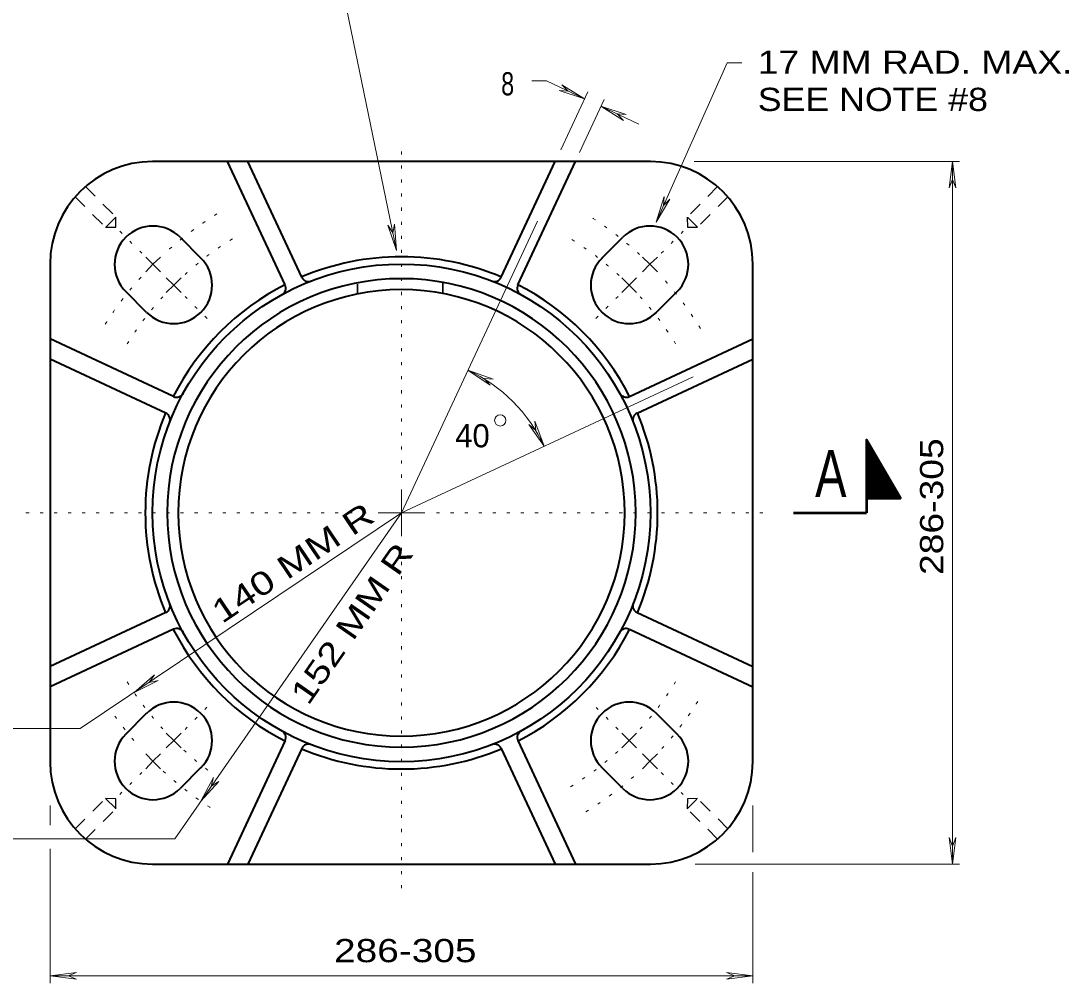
# Model space of a CAD drawing. Extents: x 312583 to 312854, y 144419 to 144597.
# Drawn here: x 312679.84 to 312714.15, y 144498.77 to 144530.27 of the extents above; entities that cross this region are included whole.
import ezdxf
from ezdxf.enums import TextEntityAlignment as Align

# ---------------------------------------------------------------- set-up
doc = ezdxf.new("R2010")
doc.units = 0
doc.header["$LTSCALE"] = 0.3
doc.linetypes.add('DOTTED', pattern=[1.5, 0.3, -1.2])
doc.linetypes.add('SHORT_DASHED', pattern=[2.7, 1.5, -1.2])
doc.layers.add('1', color=7, linetype='Continuous', lineweight=35)
doc.layers.add('2', color=7, linetype='Continuous', lineweight=13)

msp = doc.modelspace()

# ---------------------------------------------------------------- linework, layer by layer
at = {"layer": '1', "lineweight": 40}
for p, q in [((312692.2955, 144525.6633), (312684.1535, 144525.6633)), ((312688.4851, 144521.623), (312686.5991, 144525.6633)), ((312689.0295, 144521.876), (312687.2661, 144525.6633)), ((312700.4451, 144525.6633), (312692.2955, 144525.6633)), ((312695.5615, 144521.876), (312697.3248, 144525.6633)), ((312696.1058, 144521.623), (312697.9918, 144525.6633)), ((312685.0505, 144523.187), (312685.7328, 144522.5046)), ((312698.8581, 144522.5046), (312699.5405, 144523.187)), ((312680.7955, 144522.3053), (312680.7955, 144514.1633)), ((312703.7955, 144514.1633), (312703.7955, 144522.3053)), ((312683.9541, 144520.726), (312683.2718, 144521.4083)), ((312701.3191, 144521.4083), (312700.6368, 144520.726)), ((312684.8358, 144517.9736), (312680.7955, 144519.8596)), ((312699.7551, 144517.9736), (312703.7955, 144519.8596)), ((312684.5828, 144517.4293), (312680.7955, 144519.1926)), ((312700.0081, 144517.4293), (312703.7955, 144519.1926)), ((312680.7955, 144514.1633), (312680.7955, 144506.0136)), ((312703.7955, 144506.0136), (312703.7955, 144514.1633)), ((312684.5828, 144510.8973), (312680.7955, 144509.134)), ((312700.0081, 144510.8973), (312703.7955, 144509.134)), ((312684.8358, 144510.353), (312680.7955, 144508.467)), ((312699.7551, 144510.353), (312703.7955, 144508.467)), ((312683.2718, 144506.9183), (312683.9541, 144507.6006)), ((312700.6368, 144507.6006), (312701.3191, 144506.9183)), ((312688.4851, 144506.7036), (312686.5991, 144502.6633)), ((312689.0295, 144506.4506), (312687.2661, 144502.6633)), ((312695.5615, 144506.4506), (312697.3248, 144502.6633)), ((312696.1058, 144506.7036), (312697.9918, 144502.6633)), ((312685.7328, 144505.822), (312685.0505, 144505.1396)), ((312699.5405, 144505.1396), (312698.8581, 144505.822)), ((312684.1535, 144502.6633), (312692.2955, 144502.6633)), ((312692.2955, 144502.6633), (312700.4451, 144502.6633))]:
    msp.add_line(p, q, dxfattribs=at)
at = {"layer": '1', "linetype": 'SHORT_DASHED', "lineweight": 25}
for p, q in [((312681.9531, 144524.843), (312682.9498, 144523.8463)), ((312702.6378, 144524.843), (312701.6488, 144523.8463)), ((312681.6158, 144524.5056), (312682.6125, 144523.509)), ((312702.9751, 144524.5056), (312701.9861, 144523.509)), ((312681.6158, 144503.821), (312682.6125, 144504.81)), ((312702.9751, 144503.821), (312701.9861, 144504.81)), ((312681.9531, 144503.4836), (312682.9498, 144504.4726)), ((312702.6378, 144503.4836), (312701.6488, 144504.4726))]:
    msp.add_line(p, q, dxfattribs=at)
for points in [[(312682.9498, 144523.8463), (312682.6125, 144523.509), (312682.9421, 144523.5166)], [(312701.9861, 144523.509), (312701.6488, 144523.8463), (312701.6565, 144523.5166)], [(312682.6125, 144504.81), (312682.9498, 144504.4726), (312682.9421, 144504.8023)], [(312701.6488, 144504.4726), (312701.9861, 144504.81), (312701.6565, 144504.8023)]]:
    msp.add_lwpolyline(points, close=True, dxfattribs=at)
at = {"layer": '1', "lineweight": 40}
for centre, radius, start, end in [((312684.1496, 144522.3072), 3.3542, 90, 180), ((312700.4413, 144522.3072), 3.3542, 0, 90), ((312684.163, 144522.2938), 1.2578, 45, 225), ((312700.4279, 144522.2938), 1.2578, 315, 135), ((312684.8416, 144521.6153), 1.2578, 225, 45), ((312692.2955, 144514.1614), 8.3854, 90, 112.94673), ((312692.2879, 144514.1611), 8.3854, 67, 89.94673), ((312699.7494, 144521.6153), 1.2578, 135, 315), ((312689.2485, 144521.9736), 0.2396, 205.00333, 291.30722), ((312695.3425, 144521.9736), 0.2396, 248.69278, 334.99667), ((312692.2955, 144514.1614), 7.6667, 90, 180), ((312692.2955, 144514.1614), 8.3854, 117.05705, 152.95096), ((312688.2701, 144521.5175), 0.2396, 298.68804, 25.01264), ((312692.2955, 144514.1614), 7.6667, 0, 90), ((312696.3208, 144521.5175), 0.2396, 154.98736, 241.31196), ((312692.2955, 144514.1614), 8.3854, 27.05705, 62.95096), ((312692.2955, 144514.1614), 7.3073, 90, 180), ((312692.2955, 144514.1614), 7.3073, 0, 90), ((312684.9394, 144518.1867), 0.2396, 244.98736, 331.31196), ((312699.6515, 144518.1867), 0.2396, 208.68804, 295.01264), ((312692.2955, 144514.1614), 8.3854, 157.05327, 180), ((312684.4832, 144517.2084), 0.2396, 338.69278, 64.99667), ((312700.1077, 144517.2084), 0.2396, 115.00333, 201.30722), ((312692.2955, 144514.1614), 8.3854, 0, 22.94673), ((312692.2955, 144514.1614), 8.3854, 180, 202.94673), ((312692.2955, 144514.1614), 7.6667, 180, 270), ((312692.2955, 144514.1614), 7.3073, 180, 270), ((312692.2955, 144514.1614), 7.6667, 270, 0), ((312692.2955, 144514.1614), 7.3073, 270, 0), ((312692.2955, 144514.1614), 8.3854, 337.05327, 0), ((312684.4832, 144511.1144), 0.2396, 295.00333, 21.30722), ((312700.1077, 144511.1144), 0.2396, 158.69278, 244.99667), ((312692.2955, 144514.1614), 8.3854, 207.05705, 242.95096), ((312684.9394, 144510.136), 0.2396, 28.68804, 115.01264), ((312692.2955, 144514.1614), 8.3854, 297.05705, 332.95096), ((312699.6515, 144510.136), 0.2396, 64.98736, 151.31196), ((312684.8416, 144506.7075), 1.2578, 315, 135), ((312699.7494, 144506.7075), 1.2578, 45, 225), ((312684.163, 144506.029), 1.2578, 135, 315), ((312688.2701, 144506.8053), 0.2396, 334.98736, 61.31196), ((312696.3208, 144506.8053), 0.2396, 118.68804, 205.01264), ((312700.4279, 144506.029), 1.2578, 225, 45), ((312692.2955, 144514.1614), 8.3854, 247.05327, 270), ((312689.2485, 144506.3491), 0.2396, 68.69278, 154.99667), ((312692.2955, 144514.1614), 8.3854, 270, 292.94673), ((312695.3425, 144506.3491), 0.2396, 25.00333, 111.30722), ((312684.1496, 144506.0156), 3.3542, 180, 270), ((312700.4413, 144506.0156), 3.3542, 270, 0)]:
    msp.add_arc(centre, radius, start, end, dxfattribs=at)
at = {"layer": '1', "linetype": 'DOTTED', "lineweight": 13}
for radius, start, end in [(11.5, 121.67302, 132.67646), (11.5, 47.32354, 58.32698), (10.5417, 121.67021, 132.50277), (10.5417, 47.49723, 58.32979), (11.5, 137.83702, 148.35019), (11.5, 31.64981, 42.16298), (10.5417, 137.83921, 148.35431), (10.5417, 31.64569, 42.16079), (10.5417, 211.64569, 222.16079), (10.5417, 317.83921, 328.35431), (11.5, 317.83702, 328.35019), (11.5, 215.3347, 222.16255), (10.5417, 227.49787, 233.37708), (10.5417, 301.67021, 312.50277), (11.5, 227.32354, 238.32698), (11.5, 301.67302, 312.67646)]:
    msp.add_arc((312692.2955, 144514.1614), radius, start, end, dxfattribs=at)
at = {"layer": '2'}
for p, q in [((312697.0411, 144528.3006), (312696.5581, 144528.3006)), ((312698.2831, 144527.718), (312697.0411, 144528.3006)), ((312697.5471, 144528.178), (312697.7541, 144527.9633)), ((312698.2831, 144527.718), (312697.5471, 144528.178)), ((312697.4551, 144527.9863), (312697.7541, 144527.9633)), ((312698.2831, 144527.718), (312697.4551, 144527.9863)), ((312697.5088, 144526.0466), (312698.3905, 144527.948)), ((312698.1221, 144525.9546), (312698.9348, 144527.695)), ((312698.8198, 144527.4726), (312700.0695, 144526.89)), ((312698.8198, 144527.4726), (312699.6478, 144527.2043)), ((312698.8198, 144527.4726), (312699.5635, 144527.005)), ((312699.6478, 144527.2043), (312699.3565, 144527.2196)), ((312699.5635, 144527.005), (312699.3565, 144527.2196)), ((312701.8788, 144525.6633), (312710.5651, 144525.6633)), ((312710.3275, 144525.6633), (312710.2201, 144524.797)), ((312710.3275, 144525.6633), (312710.4348, 144524.797)), ((312710.2201, 144524.797), (312710.3275, 144525.073)), ((312710.4348, 144524.797), (312710.3275, 144525.073)), ((312700.6368, 144523.6776), (312700.8898, 144524.5133)), ((312700.6368, 144523.6776), (312701.0815, 144524.429)), ((312700.8898, 144524.5133), (312700.8745, 144524.222)), ((312701.0815, 144524.429), (312700.8745, 144524.222)), ((312692.0655, 144523.6163), (312692.0118, 144523.325)), ((312692.1345, 144522.75), (312692.0655, 144523.6163)), ((312692.2955, 144514.1633), (312696.7498, 144523.716)), ((312691.8508, 144523.578), (312692.0118, 144523.325)), ((312692.1345, 144522.75), (312691.8508, 144523.578)), ((312684.1611, 144522.2976), (312683.9235, 144522.5353)), ((312684.1611, 144522.2976), (312683.9235, 144522.0523)), ((312684.1611, 144522.2976), (312684.4065, 144522.5353)), ((312684.1611, 144522.2976), (312684.4065, 144522.0523)), ((312700.4298, 144522.2976), (312700.1845, 144522.5353)), ((312700.4298, 144522.2976), (312700.1845, 144522.0523)), ((312700.4298, 144522.2976), (312700.6751, 144522.5353)), ((312700.4298, 144522.2976), (312700.6751, 144522.0523)), ((312684.8435, 144521.6153), (312684.5981, 144521.8606)), ((312684.8435, 144521.6153), (312684.5981, 144521.37)), ((312684.8435, 144521.6153), (312685.0888, 144521.8606)), ((312684.8435, 144521.6153), (312685.0888, 144521.37)), ((312699.7475, 144521.6153), (312699.5098, 144521.8606)), ((312699.7475, 144521.6153), (312699.5098, 144521.37)), ((312699.7475, 144521.6153), (312699.9928, 144521.8606)), ((312699.7475, 144521.6153), (312699.9928, 144521.37)), ((312694.4728, 144518.8323), (312695.2011, 144518.3416)), ((312694.4728, 144518.8323), (312695.2931, 144518.5333)), ((312692.2955, 144514.1633), (312701.8481, 144518.6176)), ((312695.2011, 144518.3416), (312695.0018, 144518.564)), ((312695.2931, 144518.5333), (312695.0018, 144518.564)), ((312696.6578, 144517.161), (312696.6885, 144516.862)), ((312696.9645, 144516.3406), (312696.6578, 144517.161)), ((312696.4661, 144517.0536), (312696.6885, 144516.862)), ((312696.9645, 144516.3406), (312696.4661, 144517.0536)), ((312692.2955, 144514.1633), (312692.2955, 144514.93)), ((312692.2955, 144514.1633), (312692.2955, 144514.93)), ((312692.2955, 144514.1633), (312681.7845, 144507.1023)), ((312692.2955, 144514.1633), (312684.8741, 144503.4913)), ((312692.2955, 144514.1633), (312691.5288, 144514.1633)), ((312692.2955, 144514.1633), (312693.0621, 144514.1633)), ((312692.2955, 144514.1633), (312692.2955, 144513.3966)), ((312683.5478, 144508.283), (312684.2071, 144508.858)), ((312684.2071, 144508.858), (312684.0385, 144508.6126)), ((312683.5478, 144508.283), (312684.3298, 144508.674)), ((312684.3298, 144508.674), (312684.0385, 144508.6126)), ((312681.7845, 144507.1023), (312678.6335, 144507.1023)), ((312684.8435, 144506.7113), (312684.5981, 144506.949)), ((312684.8435, 144506.7113), (312684.5981, 144506.949)), ((312684.8435, 144506.7113), (312685.0888, 144506.949)), ((312699.7475, 144506.7113), (312699.5098, 144506.949)), ((312699.7475, 144506.7113), (312699.9928, 144506.949)), ((312684.8435, 144506.7113), (312684.5981, 144506.466)), ((312684.8435, 144506.7113), (312685.0888, 144506.466)), ((312699.7475, 144506.7113), (312699.5098, 144506.466)), ((312699.7475, 144506.7113), (312699.9928, 144506.466)), ((312684.1611, 144506.029), (312683.9235, 144506.2743)), ((312684.1611, 144506.029), (312683.9235, 144506.2743)), ((312684.1611, 144506.029), (312684.4065, 144506.2743)), ((312700.4298, 144506.029), (312700.1845, 144506.2743)), ((312700.4298, 144506.029), (312700.6751, 144506.2743)), ((312684.1611, 144506.029), (312683.9235, 144505.7836)), ((312684.1611, 144506.029), (312684.4065, 144505.7836)), ((312700.4298, 144506.029), (312700.1845, 144505.7836)), ((312700.4298, 144506.029), (312700.6751, 144505.7836)), ((312685.7328, 144504.718), (312686.1391, 144505.4923)), ((312686.1391, 144505.4923), (312686.0701, 144505.2086)), ((312685.7328, 144504.718), (312686.3155, 144505.3696)), ((312686.3155, 144505.3696), (312686.0701, 144505.2086)), ((312680.7955, 144504.58), (312680.7955, 144503.936)), ((312703.7955, 144504.58), (312703.7955, 144503.0543)), ((312684.8741, 144503.4913), (312678.6335, 144503.4913)), ((312710.2201, 144503.5296), (312710.3275, 144503.2536)), ((312710.3275, 144502.6633), (312710.2201, 144503.5296)), ((312710.4348, 144503.5296), (312710.3275, 144503.2536)), ((312710.3275, 144502.6633), (312710.4348, 144503.5296)), ((312680.7955, 144503.1616), (312680.7955, 144498.7686)), ((312701.9095, 144502.6633), (312710.5651, 144502.6633)), ((312703.7955, 144502.4026), (312703.7955, 144498.7686)), ((312680.7955, 144499.0063), (312681.6618, 144499.1136)), ((312680.7955, 144499.0063), (312703.7955, 144499.0063)), ((312680.7955, 144499.0063), (312681.6618, 144498.899)), ((312681.6618, 144499.1136), (312681.3858, 144499.0063)), ((312681.6618, 144498.899), (312681.3858, 144499.0063)), ((312702.9291, 144499.1136), (312703.2051, 144499.0063)), ((312703.7955, 144499.0063), (312702.9291, 144499.1136)), ((312702.9291, 144498.899), (312703.2051, 144499.0063)), ((312703.7955, 144499.0063), (312702.9291, 144498.899))]:
    msp.add_line(p, q, dxfattribs=at)
at = {"layer": '2', "linetype": 'DOTTED'}
for p, q in [((312692.2955, 144515.3133), (312692.2955, 144526.338)), ((312683.8008, 144522.658), (312683.0265, 144523.4323)), ((312700.7978, 144522.658), (312701.5645, 144523.4323)), ((312685.2115, 144521.2473), (312686.0701, 144520.3886)), ((312699.3871, 144521.2473), (312698.5208, 144520.3886)), ((312691.1455, 144514.1633), (312679.9215, 144514.1633)), ((312693.4455, 144514.1633), (312704.4548, 144514.1633)), ((312692.2955, 144513.0133), (312692.2955, 144501.8736)), ((312685.2115, 144507.0716), (312686.0701, 144507.938)), ((312699.3871, 144507.0716), (312698.5208, 144507.938)), ((312683.8008, 144505.661), (312683.0265, 144504.8943)), ((312700.7978, 144505.661), (312701.5645, 144504.8943))]:
    msp.add_line(p, q, dxfattribs=at)
at = {"layer": '2', "lineweight": 35}
for p, q in [((312690.8541, 144521.324), (312690.8541, 144521.6536)), ((312693.6525, 144521.3623), (312693.6525, 144521.738)), ((312707.5138, 144516.54), (312707.5291, 144516.54)), ((312707.5138, 144516.5093), (312707.5368, 144516.517)), ((312707.5138, 144516.4786), (312707.5521, 144516.5016)), ((312707.5138, 144516.4556), (312707.5598, 144516.4786)), ((312707.5138, 144516.425), (312707.5751, 144516.4556)), ((312707.5138, 144516.402), (312707.5828, 144516.4403)), ((312707.5138, 144516.3713), (312707.5981, 144516.4173)), ((312707.5138, 144516.3406), (312707.6058, 144516.3943)), ((312707.5138, 144516.31), (312707.6211, 144516.379)), ((312707.5138, 144516.287), (312707.6288, 144516.356)), ((312707.5138, 144516.264), (312707.6441, 144516.333)), ((312707.5138, 144516.2333), (312707.6518, 144516.31)), ((312707.5138, 144516.2103), (312707.6671, 144516.2946)), ((312707.5138, 144516.1796), (312707.6825, 144516.2716)), ((312707.5138, 144516.149), (312707.6901, 144516.2486)), ((312707.5138, 144516.1183), (312707.7055, 144516.2333)), ((312707.5138, 144516.0953), (312707.7208, 144516.2103)), ((312707.5138, 144516.0646), (312707.7285, 144516.1873)), ((312707.5138, 144516.0416), (312707.7438, 144516.172)), ((312707.5138, 144516.011), (312707.7515, 144516.149)), ((312707.5138, 144515.9803), (312707.7668, 144516.126)), ((312707.5138, 144515.9573), (312707.7745, 144516.1106)), ((312707.5138, 144515.9266), (312707.7898, 144516.08)), ((312707.5138, 144515.9036), (312707.7975, 144516.0646)), ((312707.5138, 144515.873), (312707.8128, 144516.0416)), ((312707.5138, 144515.8423), (312707.8205, 144516.0186)), ((312707.5138, 144515.8193), (312707.8358, 144516.0033)), ((312707.5138, 144515.7886), (312707.8435, 144515.9803)), ((312707.5138, 144515.7656), (312707.8588, 144515.9573)), ((312707.5138, 144515.735), (312707.8741, 144515.942)), ((312707.5138, 144515.712), (312707.8818, 144515.919)), ((312707.5138, 144515.6813), (312707.8971, 144515.896)), ((312707.5138, 144515.6506), (312707.9125, 144515.8806)), ((312707.5138, 144515.62), (312707.9201, 144515.8576)), ((312707.5138, 144515.597), (312707.9355, 144515.8346)), ((312707.5138, 144515.574), (312707.9431, 144515.8116)), ((312707.5138, 144515.5433), (312707.9585, 144515.7963)), ((312707.5138, 144515.5126), (312707.9661, 144515.7733)), ((312707.5138, 144515.4896), (312707.9815, 144515.7503)), ((312707.5138, 144515.459), (312707.9891, 144515.735)), ((312707.5138, 144515.4283), (312708.0045, 144515.712)), ((312707.5138, 144515.4053), (312708.0121, 144515.689)), ((312707.5138, 144515.3746), (312708.0275, 144515.6736)), ((312707.5138, 144515.344), (312708.0351, 144515.6506)), ((312707.5138, 144515.321), (312708.0505, 144515.6276)), ((312707.5138, 144515.2673), (312708.0735, 144515.5816)), ((312707.5138, 144515.2366), (312708.0888, 144515.5663)), ((312707.5138, 144515.2136), (312708.0965, 144515.5433)), ((312707.5138, 144515.183), (312708.1118, 144515.5203)), ((312707.5138, 144515.1523), (312708.1195, 144515.505)), ((312707.5138, 144515.1216), (312708.1348, 144515.482)), ((312707.5138, 144515.0986), (312708.1425, 144515.459)), ((312707.5138, 144515.0756), (312708.1578, 144515.4436)), ((312707.5138, 144515.0143), (312708.1808, 144515.3976)), ((312707.5138, 144514.9913), (312708.1885, 144515.3823)), ((312707.5138, 144514.9606), (312708.2038, 144515.3593)), ((312707.5215, 144515.2903), (312708.0658, 144515.6123)), ((312707.5215, 144515.045), (312708.1655, 144515.4206)), ((312707.5138, 144514.93), (312708.2191, 144515.3363)), ((312707.5138, 144514.907), (312708.2268, 144515.3133)), ((312707.5138, 144514.8763), (312708.2421, 144515.298)), ((312707.5138, 144514.8456), (312708.2575, 144515.275)), ((312707.5138, 144514.769), (312708.2881, 144515.2136)), ((312707.5138, 144514.7383), (312708.3035, 144515.1906)), ((312707.5138, 144514.7153), (312708.3111, 144515.1753)), ((312707.5138, 144514.6846), (312708.3265, 144515.1523)), ((312707.5138, 144514.654), (312708.3341, 144515.1293)), ((312707.5215, 144514.8226), (312708.2651, 144515.252)), ((312707.5215, 144514.792), (312708.2805, 144515.2366)), ((312707.5368, 144514.6386), (312708.3495, 144515.114)), ((312707.5905, 144514.6386), (312708.3571, 144515.0833)), ((312707.6288, 144514.6386), (312708.3725, 144515.068)), ((312707.6825, 144514.6386), (312708.3801, 144515.045)), ((312707.7285, 144514.6386), (312708.3955, 144515.022)), ((312707.7745, 144514.6386), (312708.4108, 144515.0066)), ((312707.8205, 144514.6386), (312708.4185, 144514.9836)), ((312707.8741, 144514.6386), (312708.4338, 144514.9606)), ((312707.9201, 144514.6386), (312708.4491, 144514.9453)), ((312707.9661, 144514.6386), (312708.4568, 144514.9223)), ((312708.0198, 144514.6386), (312708.4721, 144514.907)), ((312708.0658, 144514.6386), (312708.4798, 144514.884)), ((312708.1118, 144514.6386), (312708.4951, 144514.861)), ((312708.1655, 144514.6386), (312708.5028, 144514.8456)), ((312708.2115, 144514.6386), (312708.5181, 144514.815)), ((312708.2575, 144514.6386), (312708.5258, 144514.7996)), ((312708.3035, 144514.6386), (312708.5411, 144514.7766)), ((312708.3571, 144514.6386), (312708.5488, 144514.7536)), ((312708.3955, 144514.6386), (312708.5641, 144514.7383)), ((312708.4491, 144514.6386), (312708.5718, 144514.7153)), ((312708.4951, 144514.6386), (312708.5871, 144514.6923)), ((312708.5488, 144514.6386), (312708.6025, 144514.677)), ((312708.5948, 144514.6386), (312708.6101, 144514.654))]:
    msp.add_line(p, q, dxfattribs=at)
at = {"layer": '2', "lineweight": 53}
for p in [(312707.5138, 144514.6386), (312705.1218, 144514.1633)]:
    msp.add_line(p, (312707.5138, 144514.1633), dxfattribs=at)
at = {"layer": '2'}
for points in [[(312680.8338, 144535.4536), (312689.5201, 144535.4536), (312692.1345, 144522.75)], [(312700.6368, 144523.6776), (312702.9521, 144528.891), (312703.4351, 144528.891)], [(312710.3275, 144502.6633), (312710.3275, 144520.9406), (312710.3275, 144525.6633)]]:
    msp.add_lwpolyline(points, dxfattribs=at)
at = {"layer": '2', "lineweight": 53}
msp.add_lwpolyline([(312707.5138, 144514.6386), (312708.6255, 144514.6386), (312707.5138, 144516.5553)], close=True, dxfattribs=at)
at = {"layer": '2', "lineweight": 40}
msp.add_circle((312692.2955, 144514.1614), 8.1458, dxfattribs=at)
at = {"layer": '2'}
msp.add_circle((312695.527, 144517.1859), 0.1833, dxfattribs=at)
msp.add_arc((312692.2955, 144514.1614), 5.1536, 25.00431, 65.00757, dxfattribs=at)

# ---------------------------------------------------------------- texts
for s, width, p in [('17 MM RAD. MAX.', 1.2, (312703.9565, 144528.5373)), ('8', 0.75, (312695.5595, 144527.8282)), ('SEE NOTE #8', 1.15, (312703.9565, 144527.3173)), ('286-305 ', 1.25, (312690.0889, 144499.451))]:
    msp.add_text(s, height=0.76, dxfattribs=dict(at, width=width)).set_placement(p)
msp.add_text('40', height=0.76, dxfattribs=at).set_placement((312694.0539, 144516.3066))
for s, rotation, width, p in [('286-305', 90, 1.2, (312710.027, 144512.1265)), ('140 MM R', 33.904, 1.3, (312686.4216, 144510.5151)), ('152 MM R', 55.183, 1.3, (312689.2432, 144507.8257))]:
    msp.add_text(s, height=0.76, rotation=rotation, dxfattribs=dict(at, width=width)).set_placement(p)
at = {"layer": '2', "width": 0.75}
msp.add_text('A', height=1.533, dxfattribs=at).set_placement((312706.3484, 144514.6846), align=Align.CENTER)

doc.saveas('drawing.dxf')
